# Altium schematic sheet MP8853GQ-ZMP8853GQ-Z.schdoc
size 127 x 101 mm
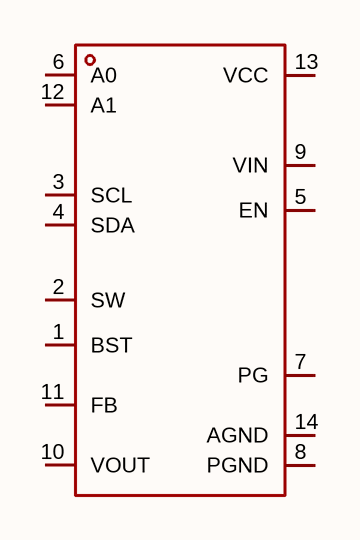
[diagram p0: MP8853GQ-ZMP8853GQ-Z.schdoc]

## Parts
U?  mp8853gq-z  [QFN-14_L3.0-W3.0-P0.50_MP8853GQ-Z]  (value not drawn)

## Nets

Not connected (* = marked no-connect by the designer): U? 1(BST) 2(SW) 3(SCL) 4(SDA) 5(EN) 6(A0) 7(PG) 8(PGND) 9(VIN) 10(VOUT) 11(FB) 12(A1) 13(VCC) 14(AGND)

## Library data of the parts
U? = mp8853gq-z: 功能类型:降压型;工作电压:2.85V~18V;输出电压:600mV~5.5V;输出电流:4A;输出类型:可调;; Manufacturer: MPS(芯源); AddInBom: yes; Function: 降压型; Output Current: 4A; Frequency - Switching: 400kHz~600kHz; Synchronous Rectifier: 是; Number of Outputs: 1; Topology: 降压式; Quiescent Current: 420uA; Switch tube (built-in/external): 内置; Output Type: 可调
